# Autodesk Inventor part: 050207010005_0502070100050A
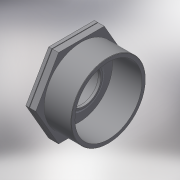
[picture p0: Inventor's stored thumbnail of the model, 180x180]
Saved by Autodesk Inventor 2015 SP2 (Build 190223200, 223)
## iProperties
Created: 2017-05
Part Number: 050207010005_0502070100050A
Material: Generic
Description: PLASSON REDUCING BUSHING 1"-1/2"
Document SubType Name: Modeling
Designer: KIM
Density: 1 g/cm^3
Appearance: Default
Author: KIM
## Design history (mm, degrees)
derived "050207.ipt"
feature "Solid1::050207.ipt"
tag "TaggingFeature1"
body "Solid1"
other parameters: "d1" = 33.249, "d2" = 36, "d5" = 19, "d8" = 0.32, "d12" = 0, "d15" = 32, "d19" = 0, "d30" = 8, "d31" = 4, "d33" = 18.631, "d34" = 29.9241, "d36" = 1.8, "d37" = 22.3572, "d38" = 21.12, "d39" = 16.7679, "d40" = 1.9, "d41" = 0, "H_" = 32, "R_" = 33.249, "E_" = 36, "l_2" = 19, "Rp_" = 18.631
